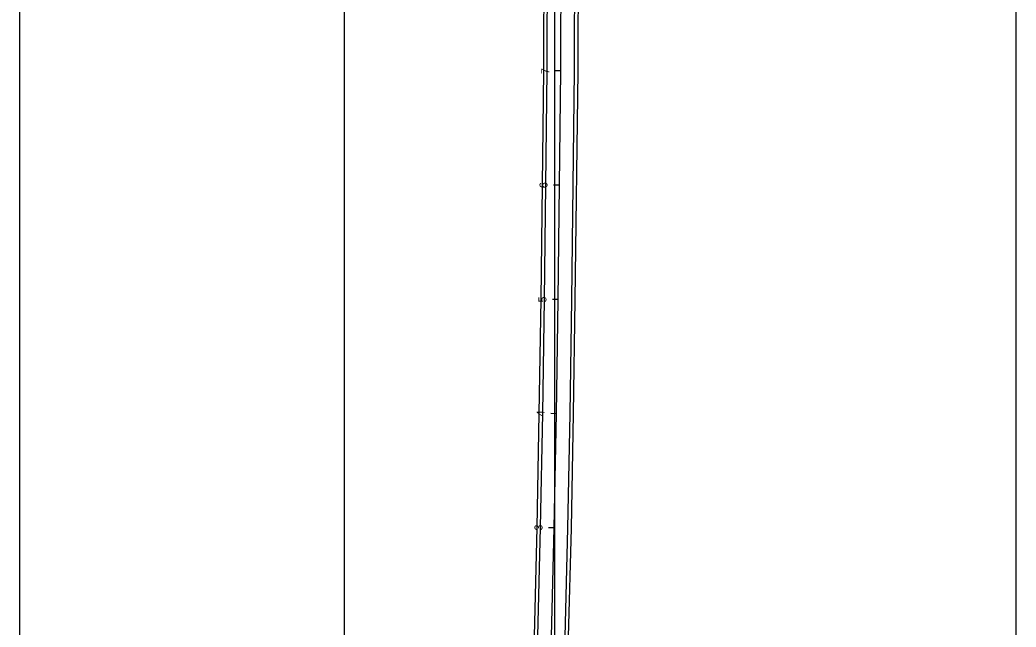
# Model space of a CAD drawing. Extents: x 2318076 to 2324211, y 613525 to 630327.
# Drawn here: x 2318413 to 2319284, y 615149 to 615680 of the extents above; entities that cross this region are included whole.
import ezdxf

# ---------------------------------------------------------------- set-up
doc = ezdxf.new("R2010")
doc.units = 0
for name, color, linetype in [('GE_P_CL_50', 7, 'Continuous'), ('PV_P_EOP', 7, 'Continuous'), ('PV_P_Shoulder', 7, 'Continuous'), ('SC_Scratch3', 7, 'Continuous')]:
    doc.layers.add(name, color=color, linetype=linetype)

msp = doc.modelspace()

# ---------------------------------------------------------------- linework, layer by layer
at = {"layer": 'GE_P_CL_50'}
for p, q in [((2318885.89, 615635.5), (2318880.89, 615635.57)), ((2318884.44, 615535.51), (2318879.44, 615535.58)), ((2318883.47, 615435.51), (2318878.47, 615435.51)), ((2318881.94, 615335.53), (2318876.94, 615335.61)), ((2318880.02, 615235.54), (2318875.02, 615235.67))]:
    msp.add_line(p, q, dxfattribs=at)
msp.add_lwpolyline([(2318877.67, 615140.55), (2318880.02, 615235.54), (2318881.94, 615335.53), (2318883.47, 615435.51), (2318885.89, 615635.5), (2318886.19, 615735.49)], dxfattribs=at)
at = {"layer": 'PV_P_EOP'}
for points in [[(2318865.67, 615140.86), (2318868.02, 615235.81), (2318869.94, 615335.73), (2318871.48, 615435.68), (2318873.89, 615635.59), (2318874.19, 615735.58)], [(2318889.67, 615140.24), (2318892.02, 615235.28), (2318893.94, 615335.32), (2318895.47, 615435.35), (2318897.89, 615635.41), (2318898.19, 615735.41)]]:
    msp.add_lwpolyline(points, dxfattribs=at)
at = {"layer": 'PV_P_Shoulder'}
for points in [[(2318862.68, 615140.94), (2318865.02, 615235.87), (2318866.94, 615335.78), (2318868.48, 615435.72), (2318870.89, 615635.61), (2318871.19, 615735.6)], [(2318892.66, 615140.16), (2318895.02, 615235.22), (2318896.94, 615335.27), (2318898.47, 615435.31), (2318900.89, 615635.38), (2318901.19, 615735.39)]]:
    msp.add_lwpolyline(points, dxfattribs=at)
at = {"layer": 'SC_Scratch3'}
for p, q in [((2318412.82, 614778.41), (2318412.82, 630327.22)), ((2318696.66, 614778.41), (2318696.66, 630327.22)), ((2318880.45, 614778.41), (2318880.45, 630327.22)), ((2319283.9, 614778.41), (2319283.9, 630327.22))]:
    msp.add_line(p, q, dxfattribs=at)

# ---------------------------------------------------------------- texts
at = {"layer": 'GE_P_CL_50'}
for s, rotation, p in [('7', 89.15268, (2318875.6, 615632.69)), ('6', 89.19307, (2318874.15, 615532.84)), ('5', 90.03366, (2318873.22, 615432.83)), ('4', 89.02682, (2318871.64, 615333.11)), ('3', 88.58318, (2318869.7, 615233.21))]:
    msp.add_text(s, height=7, rotation=rotation, dxfattribs=at).set_placement(p)

doc.saveas('drawing.dxf')
